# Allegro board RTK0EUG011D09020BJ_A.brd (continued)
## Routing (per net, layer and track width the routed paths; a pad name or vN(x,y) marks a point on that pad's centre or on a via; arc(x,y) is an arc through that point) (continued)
UG2: length 32.4
  TOP w0.203: U3.5 43.79,38.61 43.92,38.48 43.99,38.48
  TOP w0.381: v1(51.27,55.63) Q8.7
  TOP w0.508: 43.99,38.48 44.45,38.48 v1(45.1,39.13)
  L3 w0.305: v1(51.27,55.63) 51.27,59.73 52.07,60.53 TP31.1
  BOTTOM w0.508: v1(51.27,55.63) 51.18,55.53 51.18,51.16 47.78,47.75 47.78,41 45.91,39.13 v1(45.1,39.13)
VCONN: length 24.6
  TOP w0.381: Q1.6 v1(12.9,19.66) ; v1(15.81,25.45) Q4.6
  TOP w0.635: TP43.1 20.59,36.2 R141.1 20.66,36.27 R143.1
  BOTTOM w0.635: TP43.1 15.81,34.91 v1(15.81,25.45) 15.81,23.89 13.36,21.44 13.36,20.12 v1(12.9,19.66)
VCONN1_DRV: length 27.5
  TOP w0.254: v1(43.69,25.91) 43,25.22 U1.1
  TOP w0.305: v1(24.03,22.41) R28.2 21.28,22.41 Q5.1
  BOTTOM w0.305: v1(24.03,22.41) 24.64,22.41 30.35,28.12 41.73,28.12 43.66,26.19 43.66,25.93 v1(43.69,25.91)
VCONN2_DRV: length 33.4
  TOP w0.254: v1(44.4,23.98) 44.32,23.9 U1.32
  TOP w0.305: Q3.1 22.71,18.55 R16.2 23.4,18.57 24.92,20.09 v1(24.92,23.44)
  BOTTOM w0.305: v1(44.4,23.98) 44.4,26.19 42.01,28.58 30.02,28.58 24.92,23.47 v1(24.92,23.44)
N15200226: length 2.4
  TOP w0.254: U1.22 42,19.14 R2.1
N15200258: length 12.4
  TOP w0.254: U1.5 41,24.68 40.99,24.68 40.99,29.62 39.98,30.63 35.01,30.63 R56.2
N15200262: length 10
  TOP w0.254: U1.6 40.5,24.68 40.49,24.68 40.49,29.48 39.78,30.2 36.11,30.2 R54.2
N15200472: length 2.9
  TOP w0.254: R1.1 44.22,18.24 43.84,18.62 43.18,18.62 42.5,19.3 U1.23
N15200728: length 4.4
  TOP w0.254: R3.1 36.65,18.08 37.47,18.9 39.67,18.9 40,19.22 U1.18
N15200736: length 2.3
  TOP w0.254: U1.15 37.24,20.9 37.01,21.13 R5.1
N15200912: length 2.1
  TOP w0.254: C3.1 41.5,18.36 U1.21
N15284290: length 7.5
  TOP w0.152: 39.67,40.36 U3.15
  TOP w0.203: C28.2 35.43,43.99 R33.1 36.24,43.18 36.73,43.18 C27.1 38.13,41.78 38.63,41.78 39.67,40.75 39.67,40.36
N15284294: length 6.9
  TOP w0.203: C29.2 R34.1 36.94,43.63 37.24,43.33 37.98,43.33 C27.2 38.8,42.15 40.07,40.88 U3.14
N15284470: length 8.7
  TOP w0.203: U3.19 37.87,39.01 36.64,37.78 C43.2
  TOP w0.305: 31.78,37.21 R52.2 ; 31.78,37.21 R50.1 ; 31.78,37.21 34.94,37.21 C43.2
N15284522: length 2.2
  TOP w0.203: U3.29 40.87,35.01 R46.2
N15284718: length 1.4
  TOP w0.508: R47.1 39.94,33.02 C41.2
N15284978: length 4.8
  TOP w0.152: 38.72,39.81 U3.17
  TOP w0.203: 38.72,39.81 38.57,39.81 38.43,39.95
  TOP w0.508: R55.2 35.94,40.57 C44.2 36.25,40.26 38.12,40.26 38.43,39.95
N15285662: length 6.9
  TOP w0.203: U3.2 43.01,37.41 43.48,36.93 43.48,36.07 44.02,35.53 44.41,35.53 C34.1 45.05,35.95 46.08,34.92 R36.1 C36.2
N15285666: length 7.1
  TOP w0.203: U3.1 42.85,37.01 43.13,36.73 43.13,35.92 43.94,35.1 44.28,35.1 C34.2 45.09,34.56 R37.1 C37.2
N15285726: length 28.8
  TOP w0.203: v1(42.62,35.61) 42.62,35.71 42.07,36.26 U3.32
  L3 w0.508: v1(42.62,35.61) 43.03,35.2 48.41,35.2 51.92,38.71 51.92,40.06 58.06,46.2 63.68,46.2 v2(64.49,47.02)
N15285742: length 4.9
  TOP w0.203: U3.31 41.67,36.13 41.99,35.81 41.99,35.42 C33.2
  TOP w0.305: C33.2 44.12,33.29 R132.1
N15285822: length 3.7
  TOP w0.152: 42.75,39.81 U3.8
  TOP w0.203: 42.75,40.01 42.75,39.81
  TOP w0.508: 42.75,40.01 43.8,41.06 C38.2 R53.2
N15285862: length 2.9
  TOP w0.203: R49.2 37.19,35.56 38.73,35.56 39.27,36.1 U3.25
N15285922: length 2.6
  TOP w0.762: Q10.3 16.38,46.91 R32.1
N16775177: length 13.6
  TOP w0.254: C11.2 43.62,26.67 42.49,25.55 42.49,24.68 42.5,24.68 U1.2
  TOP w0.305: D2.3 37.56,28.99 v1(37.38,29.17) ; C11.2 43.65,27.2 v1(44.17,27.2) 44.17,27.21 R26.2 46,27.21 R22.1
  L3 w0.305: v1(44.17,27.2) 43.69,27.69 38.86,27.69 v1(37.38,29.17)
N16775283: length 40.8
  TOP w0.254: C9.2 v1(42.6,26.47) 41.99,25.86 41.99,24.68 42,24.68 U1.3
  TOP w0.305: v1(29.06,26.06) 10.16,26.06 9.63,25.53 8.66,25.53 RT1.2 8.03,25.55 7.56,25.08 R17.2
  BOTTOM w0.305: v1(29.06,26.06) 30.66,27.66 41.43,27.66 42.42,26.67 42.42,26.65 v1(42.6,26.47)
N16775887: length 38
  TOP w0.254: U1.4 41.5,26.43 v1(41.58,26.52) C93.2
  TOP w0.381: v1(39.75,27.09) D2.6
  BOTTOM w0.305: R118.1 R119.1 32.13,7.43 R120.2 32.14,21.83 37.4,27.09 v1(39.75,27.09) 41.01,27.09 v1(41.58,26.52) ; R118.1 R116.1 ; R118.1 R117.1
N16854744: length 26.6
  TOP w0.254: v1(37.85,21.9) U1.13
  TOP w0.305: Q2.3 v1(16.59,28.55)
  L3 w0.305: v1(37.85,21.9) 37.85,21.97 36.78,23.04 26.8,23.04 24.03,25.81 19.33,25.81 v1(16.59,28.55)
N16854902: length 3.1
  TOP w0.305: Q2.1 13.72,29.06 R15.2 R11.1
N16925191: length 4.2
  TOP w0.203: R85.2 35.92,36.55 37.97,38.61 U3.20
N16929732: length 1.5
  TOP w0.508: C94.2 13.48,33.73 R86.1
N17029936: length 8.6
  TOP w0.305: R12.2 17.71,20.31 Q1.2 14.99,20.31 v1(14.99,20.32) ; R10.1 10.56,20.11 C8.1 12.24,20.11 v1(12.46,20.33) 12.48,20.31 Q1.5
  L3 w0.305: v1(14.99,20.32) 14.99,20.31 12.48,20.31 v1(12.46,20.33)
N17029938: length 6.4
  TOP w0.305: R10.2 10.98,21.08 C8.2 12.37,21.08 12.49,20.96 Q1.4 14.1,20.96 14.4,20.66 14.4,20.05 14.78,19.66 Q1.1
N17029966: length 2
  TOP w0.305: Q3.3 17.85,19.05 R12.1
N17030035: length 7.5
  TOP w0.305: R21.1 11.01,23.71 11.45,24.15 C10.1 12.42,24.15 12.52,24.25 Q4.2 Q4.5 17.77,24.25 R25.2
N17030049: length 7.3
  TOP w0.305: v1(14.38,24.9) Q4.1 12.51,24.9 12.3,25.12 C10.2 11.78,25.1 R21.2 ; Q4.4 v1(16.51,23.6)
  L3 w0.305: v1(16.51,23.6) 15.21,24.9 v1(14.38,24.9)
N17183831: length 3.8
  TOP w0.203: U3.4 43.5,38.21 43.89,37.82
  TOP w0.508: C35.2 45.28,38.32 44.78,37.82 43.89,37.82
N17268982: length 71
  TOP w0.203: v1(38.48,36.04) 38.33,36.2 38.33,36.78 38.56,37.01 U3.24
  TOP w0.305: v1(32.77,11.81) 18.8,11.81 17.83,12.78 7.98,12.78 7.79,12.59 Q20.1 6.85,12.57 5.79,12.57 R135.1 5.13,12.57 3.35,10.8 TP39.1
  BOTTOM w0.305: v1(32.77,11.81) 33.91,11.81 39.78,17.68 42.09,17.68 48.54,24.13 48.54,29.18 44.02,33.71 41.66,33.71 40.31,35.05 39.47,35.05 v1(38.48,36.04)
N17286340: length 3.9
  TOP w0.254: C4.2 38.42,18.44 39.9,18.44 40.5,19.04 U1.19
N17317412: length 8
  TOP w0.635: R137.1 C130.2 58.23,33.97 JP48.3 TP26.1
N17341810: length 3.4
  TOP w0.203: 40.61,41.66 40.61,41.43 40.87,41.17 U3.12
  TOP w0.508: C39.2 40.61,42.68 40.61,41.66
N17357543: length 2.1
  TOP w0.305: Q17.3 20.4,48.97 20.03,49.34 R129.1
N17369918: length 2.2
  TOP w0.305: Q5.3 17.82,22.89 R25.1
N17406141: length 2
  BOTTOM w0.508: R142.1 69.85,5.13 JP31.2
N17412587: length 2.7
  TOP w0.305: D18.CATHODE R140.2
N17417629: length 1.4
  BOTTOM w0.305: SW2.1 25.65,10.19 R117.2
N17417631: length 1.4
  BOTTOM w0.305: SW2.2 28.19,10.19 R118.2
N17417633: length 1.4
  BOTTOM w0.305: SW2.4 30.73,10.19 R119.2
N17435711: length 1.7
  BOTTOM w0.305: R48A.2 SW1.1
N17435721: length 1.5
  BOTTOM w0.305: SW1.2 R48B.1
N17435729: length 46.8
  BOTTOM w0.305: v2(38.35,32.94) 37.92,32.94 34.87,29.9 25.96,29.9 15.49,19.43 SW1.8 15.49,7.11 18.03,4.57 18.03,2.16
N17435733: length 1.6
  BOTTOM w0.305: SW1.3 R48C.2
N17435747: length 1.5
  BOTTOM w0.305: R48D.2 SW1.4
N17435757: length 1.6
  BOTTOM w0.305: R48E.2 18.03,9.78
N17435769: length 1.3
  BOTTOM w0.305: R48F.2 SW1.6
N172682750: length 5
  L3 w0.305: v2(7.2,9.75) 7.2,12.93 v2(8.52,14.25)
N172682751: length 2.4
  TOP w0.305: D17.CATHODE 8.7,12.02 Q20.3
N174127601: length 1.7
  TOP w0.305: R138.1 D19.ANODE

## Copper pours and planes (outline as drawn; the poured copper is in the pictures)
+3.3V on TOP: 23.85,40.44 26.9,40.44 26.9,30.38 30.99,26.29 36.07,26.29 37.21,27.43 38.71,27.43 38.71,26.26 37.19,26.26 33.91,22.99 33.91,16.38 34.54,15.75 45.47,15.75 51.08,10.13 51.08,0.63 41.53,0.63 41.53,3.43 42.67,3.43 42.67,5.71 41.53,5.71 41.53,6.22 41.2,6.55 36.63,6.55 32.94,2.87 32.94,0.63 26.67,0.63 26.67,2.72 32.79,8.84 32.79,11.3 31.9,12.19 18.85,12.19 14.17,16.87 8,16.87 7.62,16.48 7.62,13.21 0.69,13.21 0.69,19.2 14.61,19.2 19.23,14.58 29.06,14.58 30.45,15.98 30.45,23.95 28.45,25.96 8.76,25.96 8.76,26.52 9.4,27.15 15.21,27.15 16.03,27.97 17.15,27.97 17.58,27.53 23.6,27.53 25.27,29.21 25.27,36.65 24.74,37.19 21.51,37.19 21.51,38.35 22.48,38.35 23.85,39.73
GND on TOP (solid shape): 33.23,55.65 34.17,55.65 34.17,56.05 34.47,56.05 34.47,54.39 32.93,54.39 32.93,56.05 33.23,56.05
GND on TOP (solid shape): 53.43,52.3 53.13,52.3 53.13,52.7 52.19,52.7 52.19,52.3 51.89,52.3 51.89,53.96 53.43,53.96
GND on TOP (solid shape): 23.66,41.72 24.87,41.72 24.87,41.08 23.66,41.08 23.11,40.48 19.8,40.48 19.8,42.32 23.11,42.32
GND on TOP: 0.69,67.97 85.73,67.97 85.73,0.63 0.66,0.63 0.66,29.13 4.24,29.13 4.24,28.5 5.56,28.5 5.56,29.82 8.94,29.82 8.94,38.58 0.69,38.58 ; 17 cut-outs
GND on TOP: 1.14,38.58 7.39,38.58 8.2,37.77 8.2,34.85 7.26,34.85 7.26,34.87 7.14,34.87 6.91,35.1 0.66,35.1 0.66,38.1
GND on BOTTOM: 0.64,67.94 85.73,67.94 85.73,0.63 0.64,0.63 ; 6 cut-outs
GND on L2: 0.64,67.94 0.64,0.63 85.73,0.63 85.73,67.94
GND on L3: 0.64,67.92 0.64,0.63 85.73,0.63 85.73,67.92 ; 2 cut-outs
ADP on TOP: 11.05,51.94 13.67,51.94 13.67,50.8 13.95,50.52 17.2,50.52 17.2,49.86 18.39,49.86 18.39,48.74 18.01,48.36 12.65,48.36 12.65,49.83 11.51,49.83 11.05,50.29
BATT_P on BOTTOM (solid shape): 64.06,43.64 61.67,43.64 61.67,45.39 64.06,45.39
BATT_P on TOP: 60.71,44.98 60.71,39.5 63.37,36.83 63.37,34.09 85.73,34.09 85.73,45.47 61.19,45.47
BATT_P on BOTTOM: 60.71,44.96 60.71,39.24 66.09,33.86 85.73,33.86 85.73,45.47 61.21,45.47
BATT_P1 on TOP: 60.38,46.84 64.11,46.84 65.2,47.93 65.2,50.55 59.94,50.55 59.94,47.27
BATT_P1 on BOTTOM: 60.55,49.38 64.95,49.38 65.3,49.02 65.3,47.85 65.07,47.62 63.93,47.62 63.42,47.12 63.42,45.97 61.04,45.97 60.19,46.82 60.19,49.01
CSIN1 on TOP (solid shape): 34.47,52.45 34.17,52.45 34.17,52.85 33.23,52.85 33.23,52.45 32.93,52.45 32.93,54.11 34.47,54.11
CSIN1 on TOP: 34.45,52.12 34.45,54.1 31.5,54.1 31.24,54.36 20.83,54.36 20.57,54.1 20.57,52.58 21.92,51.23 33.55,51.23
CSIN1 on BOTTOM: 34.46,51.98 34.46,54.36 20.6,54.36 20.6,52.58 22.02,51.16 33.63,51.16
CSIP1 on TOP (solid shape): 14.34,52.5 11.95,52.5 11.95,54.26 14.34,54.26
CSIP1 on TOP: 11.53,57.28 18.39,57.28 19.07,56.59 19.07,52.45 10.87,52.45 10.87,56.61
CSIP1 on BOTTOM: 11.25,52.41 18.76,52.41 19.08,52.73 19.08,56.98 18.75,57.32 11.37,57.32 10.92,56.87 10.92,52.74
CVBUS on TOP (solid shape): 14.34,46.15 11.95,46.15 11.95,47.91 14.34,47.91
CVBUS on TOP: 0.66,48.03 15.42,48.03 15.42,43.36 11.3,39.24 11.3,29.72 9.27,29.72 8.48,30.51 8.48,37.87 7.62,38.73 0.66,38.73
CVBUS on BOTTOM: 0.64,48.01 14.99,48.01 15.42,47.57 15.42,43.08 11.51,39.17 11.51,30.33 11,29.82 9.6,29.82 8.79,30.63 8.79,37.85 7.92,38.71 0.64,38.71
PH1 on TOP: 35.86,59.74 41.5,59.74 42.12,59.12 42.12,51.26 41.25,50.39 36.78,50.39 36.2,50.98 36.2,53.34 35.81,53.72 34.7,53.72 34.7,58.57
PH1 on BOTTOM: 35.86,59.74 41.5,59.74 42.11,59.13 42.11,51.23 41.25,50.37 38.38,50.37 36.65,52.1 36.65,53.7 35.99,54.36 35.23,54.36 34.67,54.91 34.67,58.55
PH2 on TOP: 44.56,59.7 49.19,59.7 50.75,58.14 50.75,54.89 50.95,54.69 51.74,54.69 51.74,52.96 51.69,52.91 51.23,52.91 48.74,50.42 44.58,50.42 43.64,51.36 43.64,58.79
PH2 on BOTTOM: 44.55,59.72 49.17,59.72 50.72,58.17 50.72,55.42 49.99,54.69 49.99,51.77 48.59,50.37 44.63,50.37 43.61,51.38 43.61,58.78
SYSV on TOP (solid shape): 52.19,55.5 53.13,55.5 53.13,55.9 53.43,55.9 53.43,54.24 51.89,54.24 51.89,55.9 52.19,55.9
SYSV on TOP: 52.68,59.05 85.75,59.05 85.75,52.27 61.44,52.27 61.44,52.91 60.44,53.91 51.92,53.91 51.92,58.29
SYSV on BOTTOM: 51.97,58.27 51.97,54.76 52.18,54.54 54.5,54.54 55.15,53.89 66.46,53.89 68.07,52.27 85.7,52.27 85.7,59.03 52.73,59.03
N15285726 on BOTTOM: 63.63,46.99 63.63,45.97 66.04,45.97 66.04,46.74 65.79,46.99 65.41,46.99 65.02,47.37 64.01,47.37

Small or netless copper shapes (teardrops, artwork), in the pictures only: 2 on TOP

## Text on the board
BOTTOM: SolderSide - Bottom
TOP: Component Side - TOP
Ref Des/Silkscreen Top: A1 | 3.3V | GND | ASGATE1 | CVBUS | ACOK | ADP | BAT CELL COUNT | VCONN | DCIN | CSIP | CSIN | DP | DM | ATTACHED_UFP | CHARGE CURRENT | RPROG | LG1 | ASGATE | UG1 | PH1 | PH2 | OTGPG | PRO# | UG2 | PSYS | VDD | IMON | COMP | LG2 | PSYS/CFG | BATT_P | SCL | SDA | SDA2 | SCL2 | INT#2 | BAT CHARGE CONTROLLER | SYSV | PD CONTROLLER | RTK0EUG011D09020BJ | REV A
L2: Internal Plane - L2
L3: Interbal etch - L3
DIMENSION: 3.  SMOBC SOLDERMASK BOTH SIDES USING BLUE RESIST. IAW IPC-SM-840 | 4.  SILKSCREEN BOTH SIDE(S) USING WHITE NON CONDUCTIVE EPOXY BASED | 1.  THIS IS A 4 LAYER BOARD WITH COMPONENTS ON BOTH SIDES. | 2.  PRINTED CIRCUIT BOARD SHALL BE 2 OUNCE COPPER. | INK. TRIM ALL SILKSCREEN 4mils FROM BARE COPPER | BOARD METERIAL TO BE EXPOXY BASED FR-4. | NOTES:
User.9: +/-10% | .062 | ADJUST CENTER CORE TO ACHIVE BOARD THICKNESS | 4 LAYER STACKING | LAYER 3 | LAYER 2 | LAYER 4 | LAYER 1 | SCALE: NONE | Top Etch 2 oz. Finished | PWR Plane 2 oz. | GND Plane 2 oz. | Bottom Etch 2 oz. Finished
User.16: X | Y
User.22: X | Y
User.45: 4-  3.2 | This document contains technical data classified EAR99 that is subject to the U.S. Export Administration Regulations (EAR).  Disclosure, transfer or use contrary to U.S. law is prohibited. | 4-NTH3.2 | NAME | RTK0EUG011D09020BJ | MARGARET SAVIEO | LAYER | DATE | REV. | PasteMask Bottom | PasteMask Top | Silkscreen Bottom | SolderMask Bottom | Silkscreen Top | SolderMask Top | 09/26/2023 | A | Internal Etch - L4 | Internal Plane - L7 | Internal Etch - L6 | Internal Etch - L5 | 09-26-23 | RTK0EUG011D09020BJ_A | MARC JOHNSON | Fabrication Drawing | N/A | 1 of 1 | VIA IN PAD MUST BE FILLED WITH NON-CONDUTIVE EPOXY | NOTE: All VIAS to be TENTED. NO exposed copper pads on any | VIAS top or bottom Except VIAS in SMT pads. | 6 . ELECTROLESS NICKEL GOLD OR IMMERSION GOLD BOARD FINISH. | 7 . MINIMUM TRACE WIDTH 8 MILS/ SPACE 6 MILS | 5 . MANUFACTURE/FABRICATE TO MEET EU RoHS DIRECTIVE. | Tg > 170 C | ALL MATERIALS AND SOLDERMASK TO BE COMPLIANT TO EU RoHS | Td > 294 C | DIRECTIVE 20002/95/EC | LAMINATE AND RESIN MATERIAL PARAMETERS | FIGURE | FINISHED_SIZE | 8.0 | 10.0 | 32.0 | 35.04 | 36.0 | 39.37 | 40.0 | 41.0 | 42.0 | 51.18 | 100.0 | 155.0 | 23.62 | 126.0 | 49.21x27.56 | 74.8x23.62 | 78.74x27.56 | 33.46x23.62 | DRILL CHART: TOP to BOTTOM | ALL UNITS ARE IN MILS | ROTATION | - | 90.000 | 0.000 | PLATED | NON-PLATED | QTY | 770 | 37 | 4 | 9 | 3 | 8 | 23 | 2 | 5 | 1 | 887 | TOTAL HOLES:
